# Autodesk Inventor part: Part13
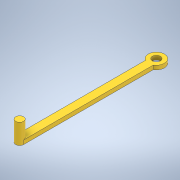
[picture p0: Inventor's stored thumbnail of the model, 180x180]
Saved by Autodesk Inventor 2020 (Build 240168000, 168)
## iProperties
Created: 2019-03
Part Number: Part13
Material: Generic
Document SubType Name: Modeling
Designer: user
Density: 1 g/cm^3
Appearance: Default
Author: user
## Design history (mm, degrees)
sketch "Sketch1"
  geometry: L1 (-412.958, 341.246)-(-412.958, 179.906); L2 (-422.958, 179.906)-(-422.958, 341.246); C1 r 5 at (-417.958, 349.906); A1 r 10 centre (-417.958, 349.906) between (-412.958, 341.246) and (-422.958, 341.246); A2 r 5 centre (-417.958, 179.906) between (-422.958, 179.906) and (-412.958, 179.906); 1 further point
  constraints: 4 end point, 4 point on circle, 3 centre point, 2 tangent, 1 coincident, 1 parallel
extrude "Extrusion1" new body sketch "Sketch1" distance "d3" = 5; taper "d4" = 0 deg
sketch "Sketch2"
  geometry: C1 r 5 at (-417.958, 179.906); A1 r 5 centre (-417.958, 179.906) between (-422.958, 179.906) and (-412.958, 179.906) reference; 1 further point
  constraints: 1 centre point, 1 coincident
extrude "Extrusion2" join sketch "Sketch2" distance "d5" = 20; taper "d6" = 0 deg
body "Solid1"
